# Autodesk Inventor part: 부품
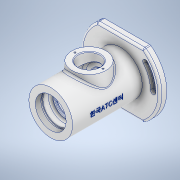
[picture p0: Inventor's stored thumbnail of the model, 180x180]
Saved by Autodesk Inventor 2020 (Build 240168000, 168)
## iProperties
Created: 2022-05
Part Number: 부품
Material: 알루미늄 6061
Document SubType Name: Modeling
Designer: Student
Density: 2.7 g/cm^3
Appearance: 알루미늄 - 평지
Mass: 686.037 g
Surface Area: 622.776 cm^2
Volume: 254.088 cm^3
Author: Student
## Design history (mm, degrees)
sketch "스케치2"
  geometry: L1 (0, 47)-(0, -47); L2 (33.985, 47)-(-33.985, 47); L3 (33.985, -47)-(-33.985, -47); L4 (0, 0)-(44.431, 37.282); L5 (0, 0)-(58, 0); L6 (0, 0)-(48, 0); L7 (0, 0)-(-48, 0); L8 (0, 0)-(-36.77, -30.854); L9 (0, 0)-(-48, 0); A1 r 58 centre (0, 0) between (-33.985, 47) and (-33.985, -47); A2 r 58 centre (0, 0) between (33.985, -47) and (33.985, 47); A3 r 48 centre (0, 0) between (48, 0) and (36.77, 30.854); A4 r 52 centre (0, 0) between (52, 0) and (39.834, 33.425); A5 r 44 centre (0, 0) between (44, 0) and (33.706, 28.283); A6 r 4 centre (48, 0) between (44, 0) and (52, 0); A7 r 4 centre (36.77, 30.854) between (39.834, 33.425) and (33.706, 28.283); A8 r 48 centre (0, 0) between (48, 0) and (36.77, 30.854); A9 r 50.25 centre (0, 0) between (50.25, 0) and (38.494, 32.3); A10 r 45.75 centre (0, 0) between (45.75, 0) and (35.047, 29.408); A11 r 2.25 centre (48, 0) between (45.75, 0) and (50.25, 0); A12 r 2.25 centre (36.77, 30.854) between (38.494, 32.3) and (35.047, 29.408); A13 r 48 centre (0, 0) between (-48, 0) and (-36.77, -30.854); A14 r 52 centre (0, 0) between (-52, 0) and (-39.834, -33.425); A15 r 44 centre (0, 0) between (-44, 0) and (-33.706, -28.283); A16 r 4 centre (-48, 0) between (-44, 0) and (-52, 0); A17 r 4 centre (-36.77, -30.854) between (-39.834, -33.425) and (-33.706, -28.283); A18 r 48 centre (0, 0) between (-48, 0) and (-36.77, -30.854); A19 r 50.25 centre (0, 0) between (-50.25, 0) and (-38.494, -32.3); A20 r 45.75 centre (0, 0) between (-45.75, 0) and (-35.047, -29.408); A21 r 2.25 centre (-48, 0) between (-45.75, 0) and (-50.25, 0); A22 r 2.25 centre (-36.77, -30.854) between (-38.494, -32.3) and (-35.047, -29.408); 3 further points
  constraints: 46 point on circle, 22 centre point, 18 end point, 17 tangent, 5 coincident, 4 midpoint, 3 horizontal, 2 point on line, 2 vertical alignment, 1 collinear, 1 equal length, 1 vertical
  dimensions: "d1" = 58 radius of A1; "d3" = 94 distance of L1.start L1.end; "d4" = 94 distance between parallel lines of L2 L3; "d5" = 47 distance from line of point (0, 0) L2; "d6" = 40 deg angle of L5 L4; "d7" = 48 radius of A3; "d8" = 4 radius of A6; "d9" = 2.25 radius of A11; "d14" = 48 radius of A13; "d15" = 40 deg angle of L9 L8; "d16" = 4 radius of A17; "d17" = 2.25 radius of A22
extrude "돌출3" new body sketch "스케치2" distance "d18" = 10; taper "d19" = 0 deg
extrude "돌출4" join sketch "스케치2" distance "d20" = 5.6; taper "d21" = 0 deg
sketch "스케치3"
  geometry: C1 r 4 at (36.77, 30.854); C2 r 4 at (-36.77, -30.854); A1 r 2.25 centre (36.77, 30.854) between (38.494, 32.3) and (35.047, 29.408) reference; A2 r 2.25 centre (-36.77, -30.854) between (-38.494, -32.3) and (-35.047, -29.408) reference; 1 further point
  constraints: 2 centre point, 2 coincident
  dimensions: "d22" = 4 radius of C1; "d23" = 4 radius of C2
extrude "돌출5" cut sketch "스케치3" extent not by distance; stored distance "d24" = 5.6; taper "d25" = 0 deg
sketch "스케치6"
  geometry: C1 r 36 at (0, 0); 1 further point
  constraints: 1 centre point, 1 coincident
  dimensions: "d26" = 36 radius of C1
extrude "돌출6" join sketch "스케치6" distance "d27" = 3; taper "d28" = 0 deg
sketch "스케치7"
  geometry: L1 (-36, -3)-(36, -3) reference; L2 (0, -3)-(0, 112); L3 (32, 112)-(32, 10); L4 (24, 104)-(24, 101); L5 (24, 101)-(22.5, 101); L6 (22.5, 101)-(22.5, 90); L7 (22.5, 90)-(17.5, 90); L8 (17.5, 90)-(17.5, 87.75); L9 (17.5, 87.75)-(18.5, 87.75); L10 (18.5, 87.75)-(18.5, 86); L11 (18.5, 86)-(17.5, 86); L12 (17.5, 86)-(17.5, 75); L13 (17.5, 75)-(27, 75); L14 (27, 75)-(27, 37); L15 (27, 37)-(17.5, 37); L16 (17.5, 37)-(17.5, 26); L17 (17.5, 26)-(15, 26); L18 (15, 26)-(15, 21); L19 (32, 112)-(22.5, 112); L20 (22.5, 112)-(22.5, 104); L21 (22.5, 104)-(24, 104); L22 (15, 21)-(11, 21); L23 (11, 21)-(11, 18.3); L24 (11, 18.3)-(15, 18.3); L25 (15, 18.3)-(15, 11.7); L26 (15, 11.7)-(15.404, 11); L27 (15.404, 11)-(20, 11); L28 (30, -3)-(20, 11); L29 (47, 10)-(-47, 10) reference; 4 further points
  constraints: 54 end point, 14 perpendicular, 8 horizontal, 3 vertical alignment, 2 midpoint, 2 vertical, 1 horizontal alignment, 1 point on line
  dimensions: "d29" = 115 distance of L2.start L2.end; "d30" = 64 diameter of L3 L2; "d31" = 102 distance of L3.start L3.end; "d34" = 3 distance of L4.start L4.end; "d35" = 11 distance of L5.end L6.end; "d36" = 48 diameter of L4 L2; "d37" = 45 diameter of L6 L2; "d38" = 2.25 distance of L7.end L8.end; "d39" = 1.75 distance of L9.end L10.end; "d40" = 11 distance of L11.end L12.end; "d41" = 35 diameter of L8 L2; "d42" = 37 diameter of L10 L2; "d43" = 38 distance of L13.end L14.end; "d44" = 54 diameter of L14 L2; "d45" = 11 distance of L15.end L16.end; "d46" = 5 distance of L17.end L18.end; "d47" = 30 diameter of L18 L2; "d48" = 45 diameter of L20 L2; "d49" = 107 distance between parallel lines of L21 L1; "d50" = 2.7 distance of L22.end L23.end; "d51" = 22 diameter of L23 L2; "d52" = 6.6 distance of L24.end L25.end; "d55" = 0.7 vertical distance of L26.end L25.end; "d56" = 30 deg angle of L26 L25; "d57" = 40 diameter of L27.end L2; "d58" = 60 diameter of L28.start L2
revolve "회전1" stored, may be unused: angle "d59" = 90 deg
revolve "회전2" stored, may be unused: angle "d60" = 360 deg
feature "스레드1" dims "d61" = 8, "d62" = 0
node "작업 평면1"
sketch "스케치8"
  geometry: L1 (-33.985, 10)-(33.985, 10) reference; L2 (-32, 112)-(32, 112) reference; C1 r 25 at (0, 56); C2 r 16 at (0, 56); 2 further points
  constraints: 2 centre point, 1 coincident, 1 midpoint, 1 vertical alignment
  dimensions: "d64" = 25 radius of C1; "d65" = 56 distance from line of C1.centre L2; "d66" = 16 radius of C2
extrude "돌출7" join sketch "스케치8" stored distance "d67" = 3; taper "d68" = 5 deg
extrude "돌출8" cut sketch "스케치8" stored distance "d69" = 3; taper "d70" = 0 deg; dims "d1" = 58, "d3" = 94, "d4" = 94, "d5" = 47, "d6" = 40 deg, "d7" = 48, "d8" = 4, "d9" = 2.25, "d14" = 48, "d15" = 40 deg, "d16" = 4, "d17" = 2.25
sketch "스케치9"
  geometry: C1 r 16 at (0, 0) reference; 2 further points
  constraints: 1 horizontal alignment
  dimensions: "d71" = 20.5 distance of C1.centre point (-20.5, 0)
hole "구멍1" sketch "스케치9" at (-20.5, 0) diameter "d72" = 2.459; stored, may be unused: countersink angle "d76" = 90 deg, drill point angle "d78" = 118 deg; dims "d73" = 6, "d74" = 4, "d75" = 2, "d77" = 8
node "작업 평면2"
sketch "스케치10"
  geometry: L1 (47, 0)-(-47, 0) reference; L2 (47, 10)-(-47, 10) reference; L3 (3.602, 86.887)-(3.602, 37.113); L4 (3.602, 37.113)-(-3.602, 37.113); L5 (-3.602, 37.113)-(-3.602, 86.887); L6 (-3.602, 86.887)-(3.602, 86.887); 2 further points
  constraints: 1 midpoint, 2 other
feature "엠보싱1" sketch "스케치10" dims "d1" = 58, "d3" = 94, "d4" = 94, "d5" = 47, "d6" = 40 deg, "d7" = 48, "d8" = 4, "d9" = 2.25, "d14" = 48, "d15" = 40 deg, "d16" = 4, "d17" = 2.25, "d81" = 0.5, "d82" = 0
sketch "스케치11"
  geometry: L1 (-25, 38)-(-26.794, 17.495) reference; L2 (25, 38)-(26.794, 17.495) reference; 1 further point
fillet "모깎기1" dims "d84" = 0.6
fillet "모깎기2" dims "d85" = 0.5
fillet "모깎기3" dims "d86" = 3
chamfer "모따기1" distance "d87" = 1; stored, may be unused: second distance "d88" = 2, angle "d89" = 45 deg
chamfer "모따기2" distance "d90" = 1; stored, may be unused: second distance "d91" = 2, angle "d92" = 45 deg
chamfer "모따기3" distance "d93" = 1; stored, may be unused: second distance "d94" = 2, angle "d95" = 45 deg
chamfer "모따기4" distance "d96" = 1; stored, may be unused: second distance "d97" = 2, angle "d98" = 45 deg
node "솔리드2"
mirror "미러1"
feature "A9D066F2-1C7D-4E18-AEED-F7BC21143FA4" dims "d72" = 2.459, "d73" = 6, "d74" = 4, "d75" = 2, "d76" = 90 deg, "d77" = 8, "d78" = 118 deg
other parameters: "d63" = 38, "d79" = 32.5
